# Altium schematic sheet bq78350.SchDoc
size 431 x 279 mm; Date: Not shown in title block; ApprovedBy: Not shown in title block; CheckedBy: Not shown in title block; Author: Not shown in title block; CompanyName: Not shown in title block; Engineer: Not shown in title block; Organization: Not shown in title block; Address1: Not shown in title block; Address2: Not shown in title block; Address3: Not shown in title block; Address4: Not shown in title block; DocumentNumber: 3; Revision: Use project parameter SCH_Rev; SheetNumber: 3; SheetTotal: 5; PageSetup: Record=PageOptions¦CenterHorizontal=True¦CenterVertical=True¦PrintScale=0.64¦XCorrection=1.00¦YCorrection=1.00¦PrintKind=0¦BorderSize=5000000¦LeftOffset=0¦BottomOffset=0¦Orientation=2¦PaperLength=1000¦PaperWidth=1000¦Scale=100¦PaperSource=15¦PrintQuality=600¦MediaType=1¦DitherType=10¦PrintScaleMode=1¦PaperKind=Letter
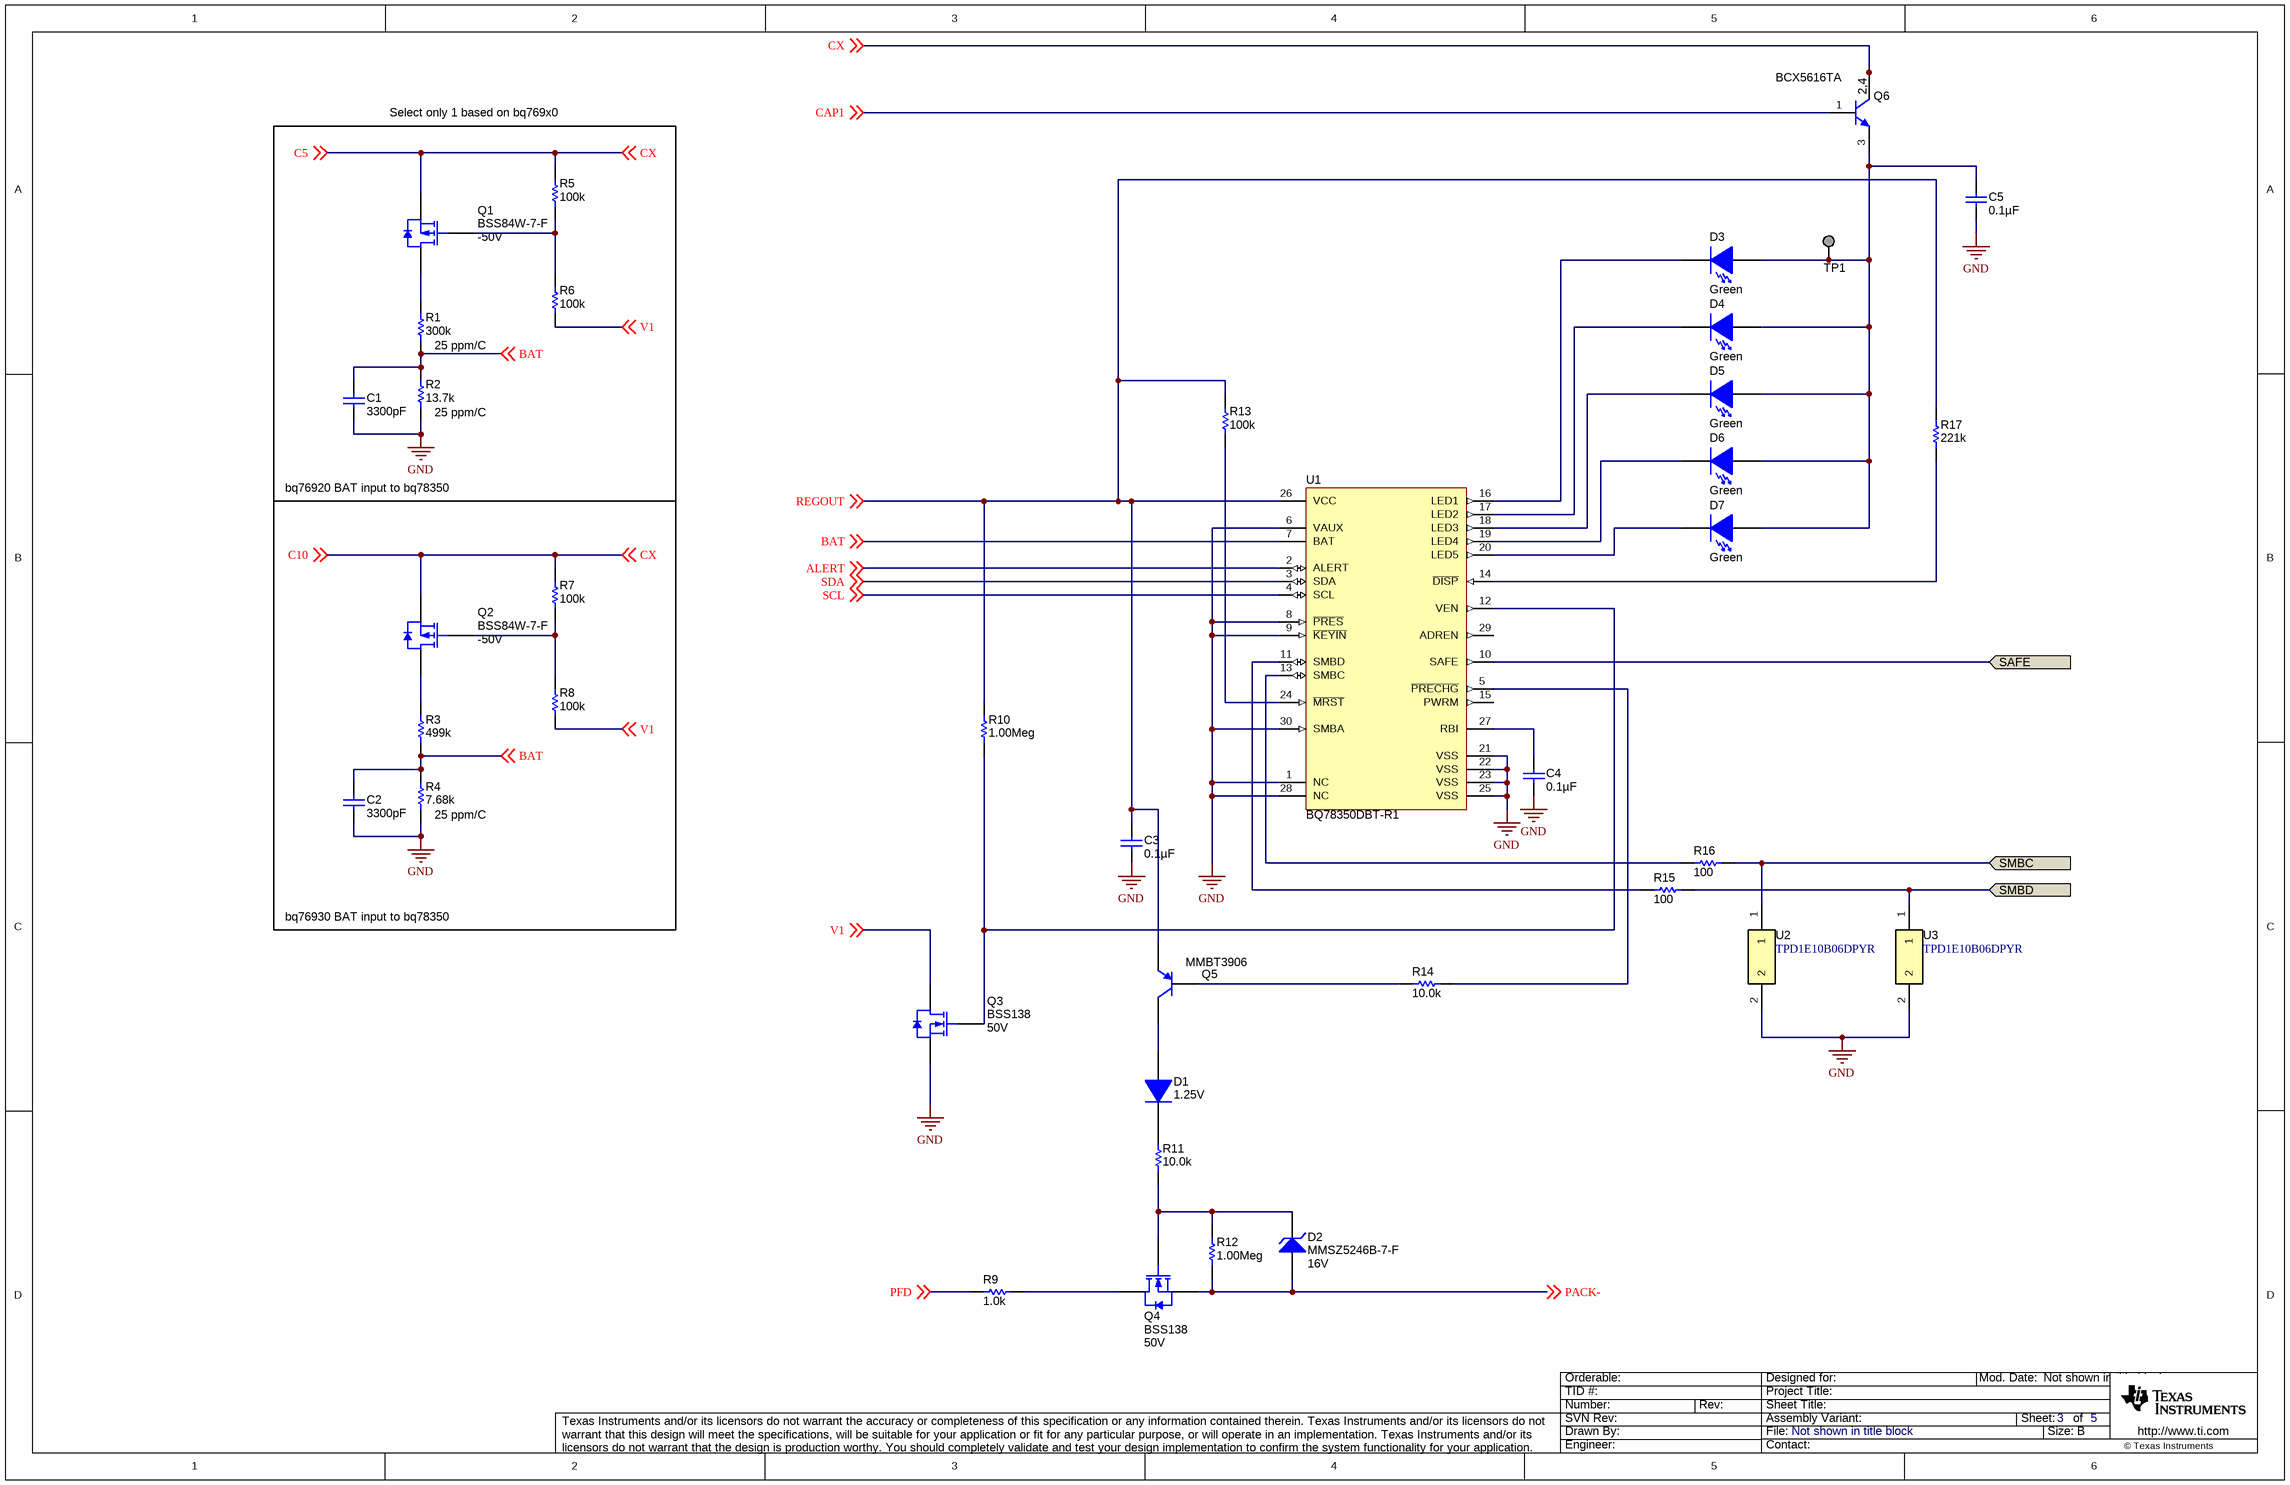
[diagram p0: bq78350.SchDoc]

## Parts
C1  ValueDisplayed: 3300pF  [0603]  (hidden comment: GRM188R71E332KA01D)
C2  ValueDisplayed: 3300pF  [0603]  (hidden comment: GRM188R71E332KA01D)
C3  ValueDisplayed: 0.1µF  [0603]  (hidden comment: GCM188R71H104KA57B)
C4  ValueDisplayed: 0.1µF  [0603]  (hidden comment: GCM188R71H104KA57B)
C5  ValueDisplayed: 0.1µF  [0603]  (hidden comment: GCM188R71H104KA57B)
D1  value 1.25V  [SOD-123]  (hidden comment: 1N4148W-7-F)
D2  MMSZ5246B-7-F  value 16V  [SOD-123]
D3  value Green  [LED_LTST-C190]  (hidden comment: LTST-C190GKT)
D4  value Green  [LED_LTST-C190]  (hidden comment: LTST-C190GKT)
D5  value Green  [LED_LTST-C190]  (hidden comment: LTST-C190GKT)
D6  value Green  [LED_LTST-C190]  (hidden comment: LTST-C190GKT)
D7  value Green  [LED_LTST-C190]  (hidden comment: LTST-C190GKT)
Q1  BSS84W-7-F  value -50V  [SOT-323]
Q2  BSS84W-7-F  value -50V  [SOT-323]
Q3  BSS138  value 50V  [SOT-23]
Q4  BSS138  value 50V  [SOT-23]
Q5  MMBT3906  [SOT-23]
Q6  BCX5616TA  [SOT-89-3]
R1  value 300k  TempCo: 25 ppm/C  [0603]  (hidden comment: RG1608P-304-B-T5)
R2  value 13.7k  TempCo: 25 ppm/C  [0603]  (hidden comment: RG1608P-1372-B-T5)
R3  ValueDisplayed: 499k  [0603]  (hidden comment: RC0603FR-07499KL)
R4  value 7.68k  TempCo: 25 ppm/C  [0603]  (hidden comment: RG1608P-7681-B-T5)
R5  value 100k  [0805_HV]  (hidden comment: CRCW0805100KFKEA)
R6  value 100k  [0805_HV]  (hidden comment: CRCW0805100KFKEA)
R7  value 100k  [0805_HV]  (hidden comment: CRCW0805100KFKEA)
R8  value 100k  [0805_HV]  (hidden comment: CRCW0805100KFKEA)
R9  value 1.0k  [2512M]  (hidden comment: ERJ-1TYJ102U)
R10  value 1.00Meg  [0805_HV]  (hidden comment: CRCW08051M00FKEA)
R11  value 10.0k  [0805_HV]  (hidden comment: CRCW080510K0FKEA)
R12  value 1.00Meg  [0805_HV]  (hidden comment: CRCW08051M00FKEA)
R13  value 100k  [0805_HV]  (hidden comment: CRCW0805100KFKEA)
R14  value 10.0k  [0805_HV]  (hidden comment: CRCW080510K0FKEA)
R15  value 100  [0805_HV]  (hidden comment: CRCW0805100RFKEA)
R16  value 100  [0805_HV]  (hidden comment: CRCW0805100RFKEA)
R17  value 221k  [0805_HV]  (hidden comment: CRCW0805221KFKEA)
TP1  (no value)  [TESTPOINT]  (no BOM)
U1  BQ78350DBT-R1  [DBT0030A_N]
U2  TPD1E10B06DPYR  [DPY0002A]
U3  TPD1E10B06DPYR  [DPY0002A]

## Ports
SAFE, SMBC, SMBD

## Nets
GND: C1.2 C2.2 C3.2 C4.2 C5.2 Q3.2(S) R2.1 R4.1 U1.1(NC) U1.6(VAUX) U1.8(~{PRES}) U1.9(~{KEYIN}) U1.21(VSS) U1.22(VSS) U1.23(VSS) U1.25(VSS) U1.28(NC) U1.30(SMBA) U2.2 U3.2
ALERT: U1.2(ALERT) ; off-sheet ALERT
BAT: C1.1 C2.1 R1.1 R2.2 R3.1 R4.2 U1.7(BAT) ; off-sheet BAT
C10: Q1.2(S) Q2.2(S) Q6.2(C) Q6.4(C) R5.1 R7.1 ; off-sheet C5, off-sheet CX, off-sheet C10  [also labelled C5, CX]
CAP1: Q6.1(B) ; off-sheet CAP1
PACK-: D2.2(A) Q4.2(S) R12.1 ; off-sheet PACK-
PFD: R9.1 ; off-sheet PFD
REGOUT: C3.1 Q5.2(E) R10.2 R13.2 R17.2 U1.26(VCC) ; off-sheet REGOUT
SAFE: U1.10(SAFE) ; port SAFE
SCL: U1.4(SCL) ; off-sheet SCL
SDA: U1.3(SDA) ; off-sheet SDA
SMBC: R16.2 U2.1 ; port SMBC
SMBD: R15.2 U3.1 ; port SMBD
V1: Q3.3(D) R6.2 R8.2 ; off-sheet V1
NetC4_1: C4.1 U1.27(RBI)
NetC5_1: C5.1 D3.1(A) D4.1(A) D5.1(A) D6.1(A) D7.1(A) Q6.3(E) TP1.1
NetD1_1: D1.1(K) R11.2
NetD1_2: D1.2(A) Q5.3(C)
NetD2_1: D2.1(K) Q4.1(G) R11.1 R12.2
NetD3_2: D3.2(K) U1.16(LED1)
NetD4_2: D4.2(K) U1.17(LED2)
NetD5_2: D5.2(K) U1.18(LED3)
NetD6_2: D6.2(K) U1.19(LED4)
NetD7_2: D7.2(K) U1.20(LED5)
NetQ1_1: Q1.1(G) R5.2 R6.1
NetQ1_3: Q1.3(D) R1.2
NetQ2_1: Q2.1(G) R7.2 R8.1
NetQ2_3: Q2.3(D) R3.2
NetQ3_1: Q3.1(G) R10.1 U1.12(VEN)
NetQ4_3: Q4.3(D) R9.2
NetQ5_1: Q5.1(B) R14.1
NetR13_1: R13.1 U1.24(~{MRST})
NetR14_2: R14.2 U1.5(~{PRECHG})
NetR15_1: R15.1 U1.11(SMBD)
NetR16_1: R16.1 U1.13(SMBC)
NetR17_1: R17.1 U1.14(~{DISP})

Not connected (* = marked no-connect by the designer): U1 15(PWRM) 29(ADREN)

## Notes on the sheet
- Select only 1 based on bq769x0
- bq76920 BAT input to bq78350
- bq76930 BAT input to bq78350

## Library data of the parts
C1 C2 = GRM188R71E332KA01D: CAP, CERM, 3300pF, 25V, +/-10%, X7R, 0603; Manufacturer: MuRata; Polarized: N; CompType: Capacitor; U/M: EA; Cap_F: 0.0000000033; Tolerance_%: 10; Value1: Unknown; VDC_V: 25; TaMin_C: -55; TaMax_C: 125
C3-C5 = GCM188R71H104KA57B: CAP, CERM, 0.1uF, 50V, +/-10%, X7R, 0603; Manufacturer: MuRata; Polarized: N; CompType: Capacitor; U/M: EA; Cap_F: 0.0000001; Tolerance_%: 10; ESR_Ohm: 0.02; Value1: 0.02 ohm; VDC_V: 50; IRMS_A: 1.84; TaMin_C: -55; TaMax_C: 125
D1 = 1N4148W-7-F: Diode, Ultrafast, 100V, 0.15A, SOD-123; Manufacturer: Diodes Inc.; U/M: EA; Vf_V: 1.25; Io_A: 0.15; Vr_V: 100; TJmax_C: 150
D2 = MMSZ5246B-7-F: Diode, Zener, 16V, 500mW, SOD-123; Manufacturer: Diodes Inc.; U/M: EA; Power_W: 0.5; Vz_V: 16; Value1: 0.5W; RJA_CperW: 350
D3-D7 = LTST-C190GKT: LED, Green, SMD; Manufacturer: Lite-On; Vf_V: 2.1; Value2: 2.1V; Io_A: 0.02; Power_TotalModule: 0.1; Value1: 0.1W; U/M: EA
Q1 Q2 = BSS84W-7-F: MOSFET, P-CH, -50V, -0.13A, SOT-323; Manufacturer: Diodes Inc.; Alternate Manufacturer: None; U/M: EA; ChType: P; VdsMax_V: -50; Value1: 10 ohm; Rdson45_Ohm: 10; Value2: ? nC; Vgs_V: -20; IdsMax_A: -0.13
Q3 Q4 = BSS138: MOSFET, N-CH, 50V, 0.22A, SOT-23; Manufacturer: Fairchild Semiconductor; Alternate Manufacturer: None; U/M: EA; ChType: N; VdsMax_V: 50; Value1: 6 ohm; Rdson45_Ohm: 6; Value2: 1.7 nC; QgTyp_nC: 1.7; Vgs_V: 20; IdsMax_A: 0.22
Q5 = MMBT3906, Fairchild Semiconductor: Transistor, PNP, 40V, 0.2A, SOT-23; Alternate Manufacturer: None; CompType: BJT; U/M: EA; PNP: 1; NPN: 0; Vceo_V: 40; Vcesat1_V: 0.25; Value: 0.25V; IcRated_A: 0.2; HfeMax: 300
Q6 = BCX5616TA, Diodes Inc.: Transistor, NPN, 80V, 1A, SOT-89; CompType: BJT; U/M: EA; PNP: 0; NPN: 1; Vceo_V: 80; Vcesat1_V: 0.5; Value: 0.5V; HfeMax: 250; TaMin_C: -65; TaMax_C: 150
R1 = RG1608P-304-B-T5: RES, 300k ohm, 0.1%, 0.1W, 0603; Manufacturer: Susumu Co Ltd; CompType: Resistor; Res_ohm: 300000; Tolerance_%: 0.1; VDC_V: 75; U/M: EA
R2 = RG1608P-1372-B-T5: RES, 13.7k ohm, 0.1%, 0.1W, 0603; Manufacturer: Susumu Co Ltd; CompType: Resistor; Res_ohm: 13700; Value_Code: 13k7; Tolerance_%: 0.1; VDC_V: 75; EIA_Code: E192; U/M: EA
R3 = RC0603FR-07499KL: RES, 499 k, 1%, 0.1 W, 0603; Manufacturer: Yageo America; CompType: Resistor; Value: 499k; Res_ohm: 499000; Tolerance_%: 1; Power_W: 0.1; Value2: 0.1W; VDC_V: 150; TempCo: 200 ppm/C; SizeArea_mm2: 1.28; SizeX_mm: 1.6; SizeY_mm: 0.8; EIA_Code: E96; U/M: EA; AEC Category: Q200
R4 = RG1608P-7681-B-T5: RES, 7.68k ohm, 0.1%, 0.1W, 0603; Manufacturer: Susumu Co Ltd; CompType: Resistor; Res_ohm: 7680; Value_Code: 7k68; Tolerance_%: 0.1; VDC_V: 75; EIA_Code: E192; U/M: EA
R5-R8 R13 = CRCW0805100KFKEA: RES, 100k ohm, 1%, 0.125W, 0805; Manufacturer: Vishay-Dale; CompType: Resistor; Res_ohm: 100000; Tolerance_%: 1; Power_W: 0.125; VDC_V: 150; TempCo: 100 ppm/C; EIA_Code: E96; U/M: EA
R9 = ERJ-1TYJ102U: RES, 1.0k ohm, 5%, 1W, 2512; Manufacturer: Panasonic; CompType: Resistor; U/M: EA; Tolerance_%: 5; Power_W: 1; TempCo: 200 ppm/C; Res_ohm: 1000; Value_Code: 1k00; VDC_V: 200; EIA_Code: E24
R10 R12 = CRCW08051M00FKEA: RES, 1.00Meg ohm, 1%, 0.125W, 0805; Manufacturer: Vishay-Dale; CompType: Resistor; Res_ohm: 1000000; Value_Code: 1M00; Tolerance_%: 1; Power_W: 0.125; VDC_V: 150; TempCo: 100 ppm/C; EIA_Code: E96; U/M: EA
R11 R14 = CRCW080510K0FKEA: RES, 10.0k ohm, 1%, 0.125W, 0805; Manufacturer: Vishay-Dale; CompType: Resistor; Res_ohm: 10000; Value_Code: 10k0; Tolerance_%: 1; Power_W: 0.125; VDC_V: 150; TempCo: 100 ppm/C; EIA_Code: E96; U/M: EA
R15 R16 = CRCW0805100RFKEA: RES, 100 ohm, 1%, 0.125W, 0805; Manufacturer: Vishay-Dale; CompType: Resistor; Value_Code: 100R; Tolerance_%: 1; Power_W: 0.125; VDC_V: 150; TempCo: 100 ppm/C; EIA_Code: E96; U/M: EA
R17 = CRCW0805221KFKEA: RES, 221k ohm, 1%, 0.125W, 0805; Manufacturer: Vishay-Dale; CompType: Resistor; Res_ohm: 221000; Tolerance_%: 1; Power_W: 0.125; VDC_V: 150; TempCo: 100 ppm/C; EIA_Code: E96; U/M: EA
TP1 = TESTPOINT: TEST POINT.  No entry in BOM.
U1 = BQ78350DBT: Companion Controller for bqMaximo AFE family with Impedance Track(TM) Fuel Gauge Technology, DBT0030A; Alternate Manufacturer: None; Manufacturer: Texas Instruments; SymbolCreator: x0208325; CompType: IC; U/M: EA
U2 U3 = TPD1E10B06DPYR: ESD in 0402 Package with 10 pF Capacitance and 6 V Breakdown, 1 Channel, -40 to +125 degC, 2-pin X2SON (DPY), Green (RoHS & no Sb/Br); Manufacturer: Texas Instruments; Alternate PartNumber: Equivalent; Breakdown Voltage(Min)(V): 6; Eco-Plan: TBD; IEC 61000-4-2 Air-Gap(+/- kV): 30; IO Capacitance(Typ)(pF): 10; SubFamily: ESD Solution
